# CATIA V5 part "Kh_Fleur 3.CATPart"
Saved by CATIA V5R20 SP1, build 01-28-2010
Part number: Fleur 3
Bounding box of the stored display mesh (mm): x 0 to 20, y -33.167 to 33.167, z -30.751 to 33.99
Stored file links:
  G:\Khaled_CFAO_2011\SIL\SIL_GR1\tmerino\Khaled\CAD_Thinkmotion\Kh_Fleur 3.CATPart
  G:\Khaled_CFAO_2011\SIL\SIL_GR1\tmerino\Khaled\CAD_Thinkmotion\Kh_Catalog.CATMaterial
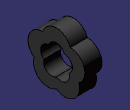
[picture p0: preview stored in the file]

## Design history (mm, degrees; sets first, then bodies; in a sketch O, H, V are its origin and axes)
Body1 (main body), material "Caoutchouc"
  Sketch1 on yz-plane, origin (0, 0, 0), H (0, 1, 0), V (0, 0, 1)
    arc A1 centre (0, 17) radius 17 from (16.168, 22.2533) to (-16.168, 22.2533) ccw
    point P2 (0, 0)
    arc A2 centre (-16.168, 5.2533) radius 17 from (-16.168, 22.2533) to (-26.1603, -8.5) ccw
    arc A3 centre (16.168, 5.2533) radius 17 from (26.1603, -8.5) to (16.168, 22.2533) ccw
    arc A4 centre (9.9923, -13.7533) radius 17 from (0, -27.5066) to (26.1603, -8.5) ccw
    arc A5 centre (-9.9923, -13.7533) radius 17 from (-26.1603, -8.5) to (0, -27.5066) ccw
    arc A6 centre (0, 9.5) radius 9.5 from (9.035, 12.4357) to (-9.035, 12.4357) ccw
    arc A7 centre (-9.035, 2.9357) radius 9.5 from (-9.035, 12.4357) to (-14.619, -4.75) ccw
    arc A8 centre (-5.584, -7.6857) radius 9.5 from (-14.619, -4.75) to (0, -15.3713) ccw
    arc A9 centre (9.035, 2.9357) radius 9.5 from (14.619, -4.75) to (9.035, 12.4357) ccw
    arc A10 centre (5.584, -7.6857) radius 9.5 from (0, -15.3713) to (14.619, -4.75) ccw
    distance A6 H = 0
  Pad1: profile Sketch1, direction (1, 0, 0), length 20
  Sketch2 on xy-plane, origin (0, 0, 0), H (1, 0, 0), V (0, 1, 0)
    axis line L1 (-10, 0) -> (40, 0)
    point P1 (-10, 0)
    coincidence: P1 H
    horizontal: L1 H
